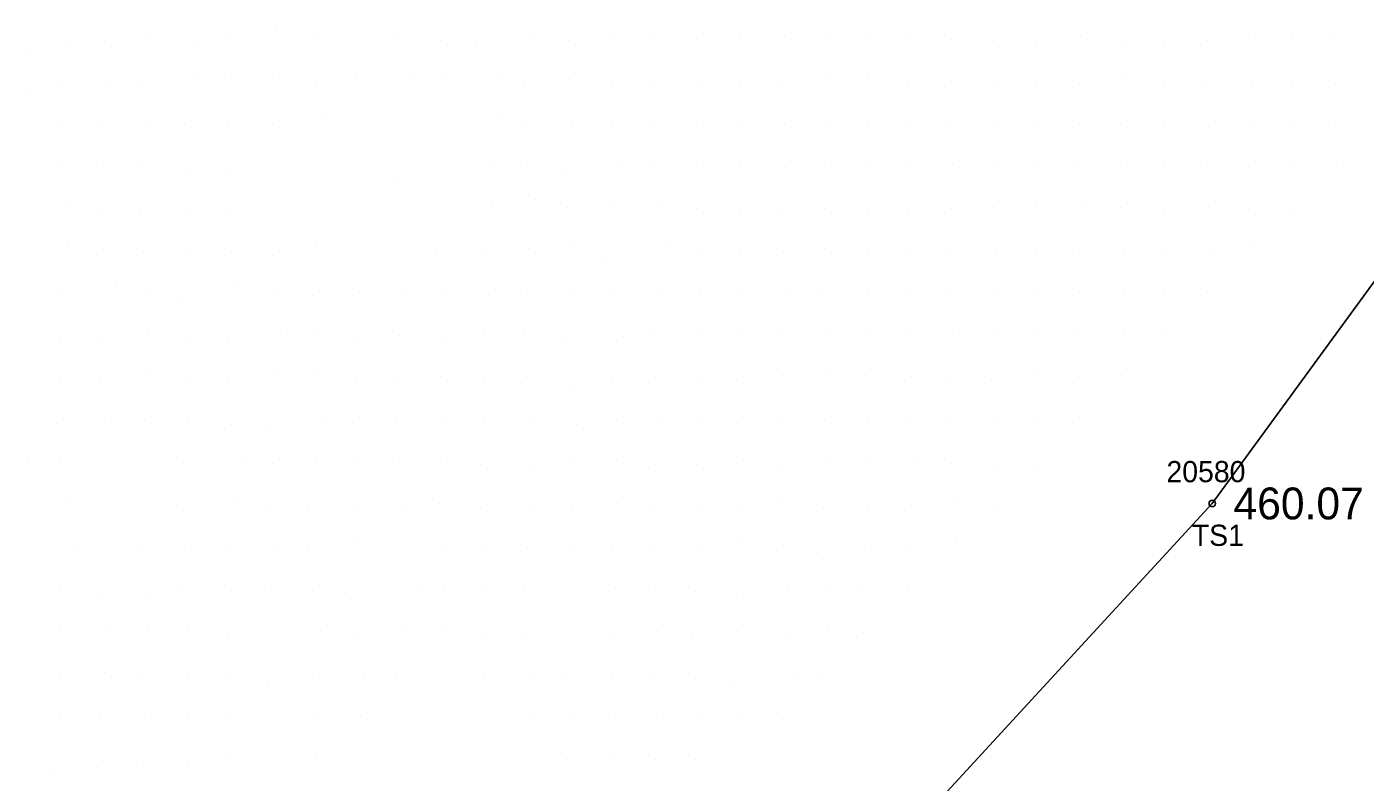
# Model space of a CAD drawing. Extents: x 1747760 to 1751131, y 649333 to 653784.
# Drawn here: x 1749176.9 to 1749239.9, y 651238.6 to 651274.2 of the extents above; entities that cross this region are included whole.
import ezdxf

# ---------------------------------------------------------------- set-up
doc = ezdxf.new("R2010")
doc.units = 0
for name, color, linetype in [('RD_DTM_BkLn2', 7, 'Continuous'), ('RD_DTM_BkLn_txCode', 7, 'Continuous'), ('RD_DTM_Spot', 7, 'Continuous'), ('RD_EX_TX_Misc_ELEV', 7, 'Continuous'), ('RD_SMD_Locator', 7, 'Continuous')]:
    doc.layers.add(name, color=color, linetype=linetype)

msp = doc.modelspace()

# ---------------------------------------------------------------- linework, layer by layer
at = {"layer": 'RD_DTM_BkLn2'}
msp.add_lwpolyline([(1749334.274, 651347.939), (1749311.737, 651326.42), (1749292.613, 651306.019), (1749271.131, 651290.935), (1749254.537, 651276.811), (1749242.73, 651265.483), (1749232.71, 651251.743), (1749211.561, 651228.743), (1749190.496, 651216.053), (1749178.766, 651203.369)], dxfattribs=at)
at = {"layer": 'RD_DTM_Spot'}
for p, q in [((1749180.542, 651273.531), (1749180.542, 651273.531)), ((1749182.539, 651273.725), (1749182.539, 651273.725)), ((1749184.918, 651273.547), (1749184.918, 651273.547)), ((1749186.441, 651273.679), (1749186.441, 651273.679)), ((1749188.646, 651273.966), (1749188.646, 651273.966)), ((1749190.382, 651273.841), (1749190.382, 651273.841)), ((1749194.366, 651273.75), (1749194.366, 651273.75)), ((1749196.354, 651273.564), (1749196.354, 651273.564)), ((1749198.062, 651273.511), (1749198.062, 651273.511)), ((1749200.585, 651273.653), (1749200.585, 651273.653)), ((1749202.4, 651273.566), (1749202.4, 651273.566)), ((1749204.495, 651273.592), (1749204.495, 651273.592)), ((1749206.399, 651273.625), (1749206.399, 651273.625)), ((1749208.432, 651273.657), (1749208.432, 651273.657)), ((1749210.492, 651273.639), (1749210.492, 651273.639)), ((1749212.559, 651273.724), (1749212.559, 651273.724)), ((1749214.519, 651273.74), (1749214.519, 651273.74)), ((1749216.363, 651273.665), (1749216.363, 651273.665)), ((1749218.458, 651273.608), (1749218.458, 651273.608)), ((1749220.444, 651273.594), (1749220.444, 651273.594)), ((1749222.418, 651273.545), (1749222.418, 651273.545)), ((1749224.406, 651273.549), (1749224.406, 651273.549)), ((1749226.508, 651273.782), (1749226.508, 651273.782)), ((1749230.419, 651273.575), (1749230.419, 651273.575)), ((1749232.499, 651273.578), (1749232.499, 651273.578)), ((1749234.435, 651273.704), (1749234.435, 651273.704)), ((1749236.468, 651273.66), (1749236.468, 651273.66)), ((1749238.485, 651273.67), (1749238.485, 651273.67)), ((1749178.888, 651273.246), (1749178.888, 651273.246)), ((1749228.433, 651273.435), (1749228.433, 651273.435)), ((1749177.023, 651272.87), (1749177.023, 651272.87)), ((1749184.721, 651271.806), (1749184.721, 651271.806)), ((1749186.545, 651271.977), (1749186.545, 651271.977)), ((1749188.47, 651271.808), (1749188.47, 651271.808)), ((1749190.524, 651271.652), (1749190.524, 651271.652)), ((1749192.361, 651271.698), (1749192.361, 651271.698)), ((1749195.122, 651271.979), (1749195.122, 651271.979)), ((1749196.441, 651271.809), (1749196.441, 651271.809)), ((1749199.034, 651271.767), (1749199.034, 651271.767)), ((1749202.421, 651271.74), (1749202.421, 651271.74)), ((1749208.483, 651271.635), (1749208.483, 651271.635)), ((1749210.486, 651271.661), (1749210.486, 651271.661)), ((1749212.458, 651271.634), (1749212.458, 651271.634)), ((1749214.541, 651271.708), (1749214.541, 651271.708)), ((1749216.478, 651271.73), (1749216.478, 651271.73)), ((1749222.48, 651271.641), (1749222.48, 651271.641)), ((1749228.484, 651271.735), (1749228.484, 651271.735)), ((1749234.599, 651271.626), (1749234.599, 651271.626)), ((1749176.888, 651271.273), (1749176.888, 651271.273)), ((1749178.512, 651271.559), (1749178.512, 651271.559)), ((1749180.651, 651271.46), (1749180.651, 651271.46)), ((1749182.284, 651271.577), (1749182.284, 651271.577)), ((1749200.348, 651271.544), (1749200.348, 651271.544)), ((1749204.446, 651271.605), (1749204.446, 651271.605)), ((1749206.42, 651271.601), (1749206.42, 651271.601)), ((1749218.411, 651271.602), (1749218.411, 651271.602)), ((1749220.449, 651271.604), (1749220.449, 651271.604)), ((1749224.38, 651271.578), (1749224.38, 651271.578)), ((1749226.463, 651271.54), (1749226.463, 651271.54)), ((1749230.418, 651271.571), (1749230.418, 651271.571)), ((1749232.441, 651271.558), (1749232.441, 651271.558)), ((1749236.5, 651271.479), (1749236.5, 651271.479)), ((1749238.493, 651271.496), (1749238.493, 651271.496)), ((1749190.778, 651270.072), (1749190.778, 651270.072)), ((1749199.264, 651269.837), (1749199.264, 651269.837)), ((1749202.593, 651269.753), (1749202.593, 651269.753)), ((1749178.55, 651269.54), (1749178.55, 651269.54)), ((1749180.454, 651269.545), (1749180.454, 651269.545)), ((1749182.47, 651269.542), (1749182.47, 651269.542)), ((1749184.338, 651269.606), (1749184.338, 651269.606)), ((1749186.375, 651269.617), (1749186.375, 651269.617)), ((1749188.471, 651269.636), (1749188.471, 651269.636)), ((1749200.418, 651269.723), (1749200.418, 651269.723)), ((1749204.418, 651269.626), (1749204.418, 651269.626)), ((1749206.433, 651269.618), (1749206.433, 651269.618)), ((1749208.418, 651269.573), (1749208.418, 651269.573)), ((1749210.528, 651269.609), (1749210.528, 651269.609)), ((1749212.551, 651269.611), (1749212.551, 651269.611)), ((1749214.481, 651269.601), (1749214.481, 651269.601)), ((1749216.48, 651269.604), (1749216.48, 651269.604)), ((1749218.499, 651269.661), (1749218.499, 651269.661)), ((1749220.354, 651269.647), (1749220.354, 651269.647)), ((1749222.438, 651269.574), (1749222.438, 651269.574)), ((1749224.511, 651269.7), (1749224.511, 651269.7)), ((1749226.47, 651269.649), (1749226.47, 651269.649)), ((1749228.395, 651269.626), (1749228.395, 651269.626)), ((1749230.448, 651269.651), (1749230.448, 651269.651)), ((1749232.51, 651269.485), (1749232.51, 651269.485)), ((1749234.453, 651269.601), (1749234.453, 651269.601)), ((1749236.54, 651269.642), (1749236.54, 651269.642)), ((1749238.531, 651269.568), (1749238.531, 651269.568)), ((1749204.708, 651267.878), (1749204.708, 651267.878)), ((1749178.54, 651267.614), (1749178.54, 651267.614)), ((1749180.489, 651267.651), (1749180.489, 651267.651)), ((1749182.3, 651267.558), (1749182.3, 651267.558)), ((1749184.432, 651267.497), (1749184.432, 651267.497)), ((1749186.449, 651267.471), (1749186.449, 651267.471)), ((1749198.88, 651267.78), (1749198.88, 651267.78)), ((1749200.477, 651267.692), (1749200.477, 651267.692)), ((1749202.276, 651267.532), (1749202.276, 651267.532)), ((1749206.395, 651267.617), (1749206.395, 651267.617)), ((1749208.435, 651267.646), (1749208.435, 651267.646)), ((1749210.507, 651267.576), (1749210.507, 651267.576)), ((1749212.617, 651267.552), (1749212.617, 651267.552)), ((1749214.472, 651267.656), (1749214.472, 651267.656)), ((1749216.447, 651267.66), (1749216.447, 651267.66)), ((1749218.473, 651267.64), (1749218.473, 651267.64)), ((1749220.478, 651267.699), (1749220.478, 651267.699)), ((1749222.417, 651267.619), (1749222.417, 651267.619)), ((1749224.48, 651267.695), (1749224.48, 651267.695)), ((1749226.392, 651267.688), (1749226.392, 651267.688)), ((1749228.375, 651267.647), (1749228.375, 651267.647)), ((1749230.448, 651267.745), (1749230.448, 651267.745)), ((1749232.464, 651267.673), (1749232.464, 651267.673)), ((1749234.416, 651267.628), (1749234.416, 651267.628)), ((1749236.527, 651267.602), (1749236.527, 651267.602)), ((1749238.542, 651267.682), (1749238.542, 651267.682)), ((1749194.16, 651266.873), (1749194.16, 651266.873)), ((1749200.83, 651266.064), (1749200.83, 651266.064)), ((1749178.696, 651265.803), (1749178.696, 651265.803)), ((1749180.402, 651265.597), (1749180.402, 651265.597)), ((1749182.215, 651265.338), (1749182.215, 651265.338)), ((1749184.381, 651265.609), (1749184.381, 651265.609)), ((1749186.474, 651265.576), (1749186.474, 651265.576)), ((1749198.763, 651265.74), (1749198.763, 651265.74)), ((1749202.373, 651265.7), (1749202.373, 651265.7)), ((1749204.379, 651265.669), (1749204.379, 651265.669)), ((1749206.61, 651265.824), (1749206.61, 651265.824)), ((1749208.423, 651265.626), (1749208.423, 651265.626)), ((1749210.488, 651265.634), (1749210.488, 651265.634)), ((1749212.474, 651265.56), (1749212.474, 651265.56)), ((1749214.43, 651265.628), (1749214.43, 651265.628)), ((1749216.492, 651265.649), (1749216.492, 651265.649)), ((1749218.397, 651265.631), (1749218.397, 651265.631)), ((1749220.453, 651265.64), (1749220.453, 651265.64)), ((1749222.391, 651265.705), (1749222.391, 651265.705)), ((1749224.432, 651265.68), (1749224.432, 651265.68)), ((1749226.536, 651265.714), (1749226.536, 651265.714)), ((1749228.409, 651265.679), (1749228.409, 651265.679)), ((1749230.454, 651265.586), (1749230.454, 651265.586)), ((1749232.545, 651265.719), (1749232.545, 651265.719)), ((1749234.429, 651265.589), (1749234.429, 651265.589)), ((1749236.521, 651265.468), (1749236.521, 651265.468)), ((1749178.824, 651263.8), (1749178.824, 651263.8)), ((1749180.505, 651263.724), (1749180.505, 651263.724)), ((1749182.377, 651263.592), (1749182.377, 651263.592)), ((1749184.431, 651263.719), (1749184.431, 651263.719)), ((1749186.506, 651263.602), (1749186.506, 651263.602)), ((1749188.471, 651263.448), (1749188.471, 651263.448)), ((1749190.499, 651263.92), (1749190.499, 651263.92)), ((1749196.186, 651263.651), (1749196.186, 651263.651)), ((1749198.546, 651263.466), (1749198.546, 651263.466)), ((1749200.537, 651263.742), (1749200.537, 651263.742)), ((1749202.62, 651263.841), (1749202.62, 651263.841)), ((1749207.027, 651263.881), (1749207.027, 651263.881)), ((1749208.515, 651263.659), (1749208.515, 651263.659)), ((1749210.504, 651263.709), (1749210.504, 651263.709)), ((1749212.498, 651263.601), (1749212.498, 651263.601)), ((1749214.448, 651263.742), (1749214.448, 651263.742)), ((1749216.454, 651263.632), (1749216.454, 651263.632)), ((1749218.434, 651263.707), (1749218.434, 651263.707)), ((1749220.401, 651263.672), (1749220.401, 651263.672)), ((1749222.493, 651263.724), (1749222.493, 651263.724)), ((1749224.442, 651263.709), (1749224.442, 651263.709)), ((1749226.447, 651263.66), (1749226.447, 651263.66)), ((1749228.514, 651263.734), (1749228.514, 651263.734)), ((1749230.374, 651263.65), (1749230.374, 651263.65)), ((1749232.651, 651263.645), (1749232.651, 651263.645)), ((1749234.493, 651263.803), (1749234.493, 651263.803)), ((1749204.161, 651263.383), (1749204.161, 651263.383)), ((1749181.067, 651262.049), (1749181.067, 651262.049)), ((1749182.54, 651261.883), (1749182.54, 651261.883)), ((1749186.65, 651261.961), (1749186.65, 651261.961)), ((1749188.53, 651261.623), (1749188.53, 651261.623)), ((1749190.342, 651261.561), (1749190.342, 651261.561)), ((1749192.546, 651261.672), (1749192.546, 651261.672)), ((1749194.543, 651261.753), (1749194.543, 651261.753)), ((1749196.415, 651261.582), (1749196.415, 651261.582)), ((1749198.608, 651261.594), (1749198.608, 651261.594)), ((1749200.467, 651261.65), (1749200.467, 651261.65)), ((1749202.432, 651261.731), (1749202.432, 651261.731)), ((1749204.533, 651261.824), (1749204.533, 651261.824)), ((1749206.583, 651261.63), (1749206.583, 651261.63)), ((1749208.614, 651261.83), (1749208.614, 651261.83)), ((1749210.542, 651261.754), (1749210.542, 651261.754)), ((1749212.595, 651261.826), (1749212.595, 651261.826)), ((1749214.351, 651261.624), (1749214.351, 651261.624)), ((1749216.455, 651261.714), (1749216.455, 651261.714)), ((1749218.491, 651261.727), (1749218.491, 651261.727)), ((1749220.405, 651261.671), (1749220.405, 651261.671)), ((1749222.458, 651261.614), (1749222.458, 651261.614)), ((1749224.47, 651261.726), (1749224.47, 651261.726)), ((1749226.436, 651261.719), (1749226.436, 651261.719)), ((1749228.554, 651261.767), (1749228.554, 651261.767)), ((1749230.467, 651261.736), (1749230.467, 651261.736)), ((1749232.49, 651261.722), (1749232.49, 651261.722)), ((1749178.369, 651261.53), (1749178.369, 651261.53)), ((1749184.239, 651261.401), (1749184.239, 651261.401)), ((1749182.593, 651259.889), (1749182.593, 651259.889)), ((1749188.826, 651259.896), (1749188.826, 651259.896)), ((1749190.561, 651259.647), (1749190.561, 651259.647)), ((1749194.451, 651259.673), (1749194.451, 651259.673)), ((1749198.446, 651259.754), (1749198.446, 651259.754)), ((1749200.289, 651259.661), (1749200.289, 651259.661)), ((1749206.405, 651259.711), (1749206.405, 651259.711)), ((1749208.459, 651259.698), (1749208.459, 651259.698)), ((1749210.604, 651259.87), (1749210.604, 651259.87)), ((1749212.472, 651259.842), (1749212.472, 651259.842)), ((1749214.483, 651259.817), (1749214.483, 651259.817)), ((1749216.382, 651259.792), (1749216.382, 651259.792)), ((1749218.5, 651259.783), (1749218.5, 651259.783)), ((1749220.484, 651259.77), (1749220.484, 651259.77)), ((1749222.398, 651259.707), (1749222.398, 651259.707)), ((1749224.533, 651259.722), (1749224.533, 651259.722)), ((1749226.399, 651259.698), (1749226.399, 651259.698)), ((1749228.553, 651259.79), (1749228.553, 651259.79)), ((1749230.5, 651259.708), (1749230.5, 651259.708)), ((1749178.454, 651259.561), (1749178.454, 651259.561)), ((1749180.232, 651259.332), (1749180.232, 651259.332)), ((1749184.397, 651259.456), (1749184.397, 651259.456)), ((1749186.379, 651259.516), (1749186.379, 651259.516)), ((1749192.342, 651259.543), (1749192.342, 651259.543)), ((1749196.443, 651259.582), (1749196.443, 651259.582)), ((1749202.253, 651259.511), (1749202.253, 651259.511)), ((1749204.974, 651259.624), (1749204.974, 651259.624)), ((1749182.508, 651257.758), (1749182.508, 651257.758)), ((1749188.672, 651257.943), (1749188.672, 651257.943)), ((1749190.635, 651257.887), (1749190.635, 651257.887)), ((1749212.468, 651257.765), (1749212.468, 651257.765)), ((1749214.564, 651257.844), (1749214.564, 651257.844)), ((1749216.394, 651257.791), (1749216.394, 651257.791)), ((1749224.466, 651257.756), (1749224.466, 651257.756)), ((1749228.423, 651257.764), (1749228.423, 651257.764)), ((1749178.498, 651257.673), (1749178.498, 651257.673)), ((1749180.298, 651257.514), (1749180.298, 651257.514)), ((1749184.384, 651257.451), (1749184.384, 651257.451)), ((1749186.392, 651257.695), (1749186.392, 651257.695)), ((1749192.403, 651257.616), (1749192.403, 651257.616)), ((1749194.377, 651257.583), (1749194.377, 651257.583)), ((1749196.352, 651257.72), (1749196.352, 651257.72)), ((1749198.378, 651257.584), (1749198.378, 651257.584)), ((1749200.402, 651257.725), (1749200.402, 651257.725)), ((1749202.443, 651257.235), (1749202.443, 651257.235)), ((1749204.407, 651257.581), (1749204.407, 651257.581)), ((1749206.517, 651257.665), (1749206.517, 651257.665)), ((1749208.69, 651257.678), (1749208.69, 651257.678)), ((1749210.301, 651257.539), (1749210.301, 651257.539)), ((1749218.569, 651257.744), (1749218.569, 651257.744)), ((1749220.318, 651257.557), (1749220.318, 651257.557)), ((1749222.313, 651257.55), (1749222.313, 651257.55)), ((1749226.415, 651257.712), (1749226.415, 651257.712)), ((1749178.297, 651255.52), (1749178.297, 651255.52)), ((1749180.56, 651255.732), (1749180.56, 651255.732)), ((1749182.451, 651255.722), (1749182.451, 651255.722)), ((1749184.455, 651255.645), (1749184.455, 651255.645)), ((1749186.532, 651255.477), (1749186.532, 651255.477)), ((1749188.325, 651255.304), (1749188.325, 651255.304)), ((1749190.831, 651255.653), (1749190.831, 651255.653)), ((1749192.539, 651255.788), (1749192.539, 651255.788)), ((1749194.32, 651255.575), (1749194.32, 651255.575)), ((1749196.48, 651255.724), (1749196.48, 651255.724)), ((1749198.431, 651255.663), (1749198.431, 651255.663)), ((1749200.552, 651255.747), (1749200.552, 651255.747)), ((1749202.752, 651255.483), (1749202.752, 651255.483)), ((1749204.678, 651255.64), (1749204.678, 651255.64)), ((1749206.576, 651255.718), (1749206.576, 651255.718)), ((1749208.494, 651255.65), (1749208.494, 651255.65)), ((1749210.357, 651255.532), (1749210.357, 651255.532)), ((1749212.469, 651255.561), (1749212.469, 651255.561)), ((1749214.455, 651255.698), (1749214.455, 651255.698)), ((1749216.541, 651255.628), (1749216.541, 651255.628)), ((1749218.463, 651255.619), (1749218.463, 651255.619)), ((1749220.344, 651255.772), (1749220.344, 651255.772)), ((1749222.59, 651255.818), (1749222.59, 651255.818)), ((1749224.487, 651255.649), (1749224.487, 651255.649)), ((1749226.447, 651255.793), (1749226.447, 651255.793)), ((1749176.926, 651253.918), (1749176.926, 651253.918)), ((1749178.491, 651253.713), (1749178.491, 651253.713)), ((1749184.287, 651253.669), (1749184.287, 651253.669)), ((1749187.02, 651253.897), (1749187.02, 651253.897)), ((1749188.438, 651253.644), (1749188.438, 651253.644)), ((1749190.525, 651253.637), (1749190.525, 651253.637)), ((1749192.48, 651253.735), (1749192.48, 651253.735)), ((1749194.444, 651253.726), (1749194.444, 651253.726)), ((1749196.349, 651253.74), (1749196.349, 651253.74)), ((1749198.256, 651253.556), (1749198.256, 651253.556)), ((1749200.582, 651253.526), (1749200.582, 651253.526)), ((1749202.491, 651253.674), (1749202.491, 651253.674)), ((1749204.662, 651253.794), (1749204.662, 651253.794)), ((1749206.179, 651253.443), (1749206.179, 651253.443)), ((1749208.436, 651253.575), (1749208.436, 651253.575)), ((1749210.647, 651253.764), (1749210.647, 651253.764)), ((1749212.215, 651253.527), (1749212.215, 651253.527)), ((1749214.476, 651253.77), (1749214.476, 651253.77)), ((1749216.433, 651253.767), (1749216.433, 651253.767)), ((1749218.647, 651253.852), (1749218.647, 651253.852)), ((1749220.433, 651253.604), (1749220.433, 651253.604)), ((1749222.438, 651253.496), (1749222.438, 651253.496)), ((1749224.343, 651253.549), (1749224.343, 651253.549)), ((1749178.7, 651251.819), (1749178.7, 651251.819)), ((1749186.806, 651251.976), (1749186.806, 651251.976)), ((1749188.168, 651251.509), (1749188.168, 651251.509)), ((1749190.175, 651251.469), (1749190.175, 651251.469)), ((1749192.283, 651251.48), (1749192.283, 651251.48)), ((1749194.595, 651251.569), (1749194.595, 651251.569)), ((1749196.329, 651251.754), (1749196.329, 651251.754)), ((1749198.271, 651251.531), (1749198.271, 651251.531)), ((1749200.587, 651251.627), (1749200.587, 651251.627)), ((1749202.57, 651251.665), (1749202.57, 651251.665)), ((1749204.682, 651251.745), (1749204.682, 651251.745)), ((1749206.25, 651251.606), (1749206.25, 651251.606)), ((1749208.534, 651251.697), (1749208.534, 651251.697)), ((1749210.558, 651251.617), (1749210.558, 651251.617)), ((1749212.426, 651251.823), (1749212.426, 651251.823)), ((1749214.389, 651251.574), (1749214.389, 651251.574)), ((1749216.517, 651251.641), (1749216.517, 651251.641)), ((1749218.553, 651251.655), (1749218.553, 651251.655)), ((1749220.742, 651251.768), (1749220.742, 651251.768)), ((1749222.408, 651251.66), (1749222.408, 651251.66)), ((1749184.279, 651251.415), (1749184.279, 651251.415)), ((1749179.134, 651249.751), (1749179.134, 651249.751)), ((1749182.349, 651249.713), (1749182.349, 651249.713)), ((1749184.303, 651249.716), (1749184.303, 651249.716)), ((1749186.43, 651249.604), (1749186.43, 651249.604)), ((1749188.499, 651249.77), (1749188.499, 651249.77)), ((1749192.438, 651249.866), (1749192.438, 651249.866)), ((1749196.64, 651249.694), (1749196.64, 651249.694)), ((1749198.482, 651249.743), (1749198.482, 651249.743)), ((1749200.453, 651249.617), (1749200.453, 651249.617)), ((1749202.624, 651249.727), (1749202.624, 651249.727)), ((1749204.458, 651249.64), (1749204.458, 651249.64)), ((1749206.386, 651249.675), (1749206.386, 651249.675)), ((1749208.501, 651249.738), (1749208.501, 651249.738)), ((1749210.553, 651250.014), (1749210.553, 651250.014)), ((1749212.5, 651249.756), (1749212.5, 651249.756)), ((1749216.343, 651249.718), (1749216.343, 651249.718)), ((1749218.267, 651249.643), (1749218.267, 651249.643)), ((1749220.672, 651249.946), (1749220.672, 651249.946)), ((1749190.17, 651249.522), (1749190.17, 651249.522)), ((1749214.123, 651249.444), (1749214.123, 651249.444)), ((1749184.211, 651247.69), (1749184.211, 651247.69)), ((1749188.427, 651247.673), (1749188.427, 651247.673)), ((1749195.288, 651247.703), (1749195.288, 651247.703)), ((1749196.526, 651247.787), (1749196.526, 651247.787)), ((1749198.486, 651247.7), (1749198.486, 651247.7)), ((1749204.613, 651247.756), (1749204.613, 651247.756)), ((1749206.509, 651247.709), (1749206.509, 651247.709)), ((1749212.734, 651247.936), (1749212.734, 651247.936)), ((1749214.484, 651247.734), (1749214.484, 651247.734)), ((1749178.407, 651247.625), (1749178.407, 651247.625)), ((1749180.27, 651247.348), (1749180.27, 651247.348)), ((1749182.481, 651247.299), (1749182.481, 651247.299)), ((1749186.505, 651247.66), (1749186.505, 651247.66)), ((1749190.365, 651247.663), (1749190.365, 651247.663)), ((1749192.125, 651247.215), (1749192.125, 651247.215)), ((1749200.316, 651247.641), (1749200.316, 651247.641)), ((1749208.384, 651247.597), (1749208.384, 651247.597)), ((1749210.294, 651247.462), (1749210.294, 651247.462)), ((1749216.224, 651247.646), (1749216.224, 651247.646)), ((1749218.368, 651247.611), (1749218.368, 651247.611)), ((1749178.485, 651246.031), (1749178.485, 651246.031)), ((1749180.631, 651245.792), (1749180.631, 651245.792)), ((1749191.05, 651245.987), (1749191.05, 651245.987)), ((1749214.578, 651245.806), (1749214.578, 651245.806)), ((1749182.633, 651245.761), (1749182.633, 651245.761)), ((1749184.446, 651245.758), (1749184.446, 651245.758)), ((1749186.334, 651245.553), (1749186.334, 651245.553)), ((1749192.341, 651245.476), (1749192.341, 651245.476)), ((1749194.586, 651245.775), (1749194.586, 651245.775)), ((1749196.461, 651245.722), (1749196.461, 651245.722)), ((1749198.541, 651245.568), (1749198.541, 651245.568)), ((1749200.375, 651245.568), (1749200.375, 651245.568)), ((1749204.519, 651245.59), (1749204.519, 651245.59)), ((1749206.572, 651245.701), (1749206.572, 651245.701)), ((1749208.227, 651245.504), (1749208.227, 651245.504)), ((1749210.374, 651245.707), (1749210.374, 651245.707)), ((1749212.656, 651245.636), (1749212.656, 651245.636)), ((1749216.297, 651245.653), (1749216.297, 651245.653)), ((1749178.494, 651243.658), (1749178.494, 651243.658)), ((1749180.548, 651243.8), (1749180.548, 651243.8)), ((1749182.294, 651243.546), (1749182.294, 651243.546)), ((1749184.526, 651243.628), (1749184.526, 651243.628)), ((1749186.496, 651243.709), (1749186.496, 651243.709)), ((1749188.292, 651243.345), (1749188.292, 651243.345)), ((1749190.329, 651243.519), (1749190.329, 651243.519)), ((1749192.743, 651243.8), (1749192.743, 651243.8)), ((1749194.28, 651243.476), (1749194.28, 651243.476)), ((1749198.434, 651243.485), (1749198.434, 651243.485)), ((1749200.618, 651243.542), (1749200.618, 651243.542)), ((1749202.261, 651243.61), (1749202.261, 651243.61)), ((1749204.459, 651243.728), (1749204.459, 651243.728)), ((1749206.424, 651243.659), (1749206.424, 651243.659)), ((1749208.358, 651243.508), (1749208.358, 651243.508)), ((1749210.191, 651243.292), (1749210.191, 651243.292)), ((1749212.996, 651243.669), (1749212.996, 651243.669)), ((1749214.333, 651243.495), (1749214.333, 651243.495)), ((1749178.456, 651241.617), (1749178.456, 651241.617)), ((1749180.338, 651241.661), (1749180.338, 651241.661)), ((1749182.413, 651241.658), (1749182.413, 651241.658)), ((1749184.5, 651241.703), (1749184.5, 651241.703)), ((1749186.468, 651241.798), (1749186.468, 651241.798)), ((1749190.576, 651241.715), (1749190.576, 651241.715)), ((1749192.626, 651241.762), (1749192.626, 651241.762)), ((1749200.62, 651241.844), (1749200.62, 651241.844)), ((1749202.479, 651241.618), (1749202.479, 651241.618)), ((1749204.273, 651241.679), (1749204.273, 651241.679)), ((1749206.531, 651241.637), (1749206.531, 651241.637)), ((1749208.475, 651241.586), (1749208.475, 651241.586)), ((1749210.415, 651241.638), (1749210.415, 651241.638)), ((1749212.469, 651241.548), (1749212.469, 651241.548)), ((1749180.476, 651239.638), (1749180.476, 651239.638)), ((1749182.401, 651239.539), (1749182.401, 651239.539)), ((1749184.436, 651239.573), (1749184.436, 651239.573)), ((1749186.301, 651239.684), (1749186.301, 651239.684)), ((1749190.55, 651239.906), (1749190.55, 651239.906)), ((1749202.326, 651239.676), (1749202.326, 651239.676)), ((1749204.581, 651239.757), (1749204.581, 651239.757)), ((1749206.516, 651239.662), (1749206.516, 651239.662)), ((1749208.397, 651239.656), (1749208.397, 651239.656)), ((1749178.148, 651239.219), (1749178.148, 651239.219))]:
    msp.add_line(p, q, dxfattribs=at)
at = {"layer": 'RD_SMD_Locator'}
msp.add_circle((1749232.71, 651251.743), 0.15, dxfattribs=at)

# ---------------------------------------------------------------- texts
at = {"layer": 'RD_DTM_BkLn_txCode'}
for s, p in [('20580', (1749230.553, 651252.743)), ('TS1', (1749231.749, 651249.743))]:
    msp.add_text(s, height=1, dxfattribs=at).set_placement(p)
at = {"layer": 'RD_EX_TX_Misc_ELEV'}
msp.add_text('460.07', height=1.5, dxfattribs=at).set_placement((1749233.71, 651250.993))

doc.saveas('drawing.dxf')
